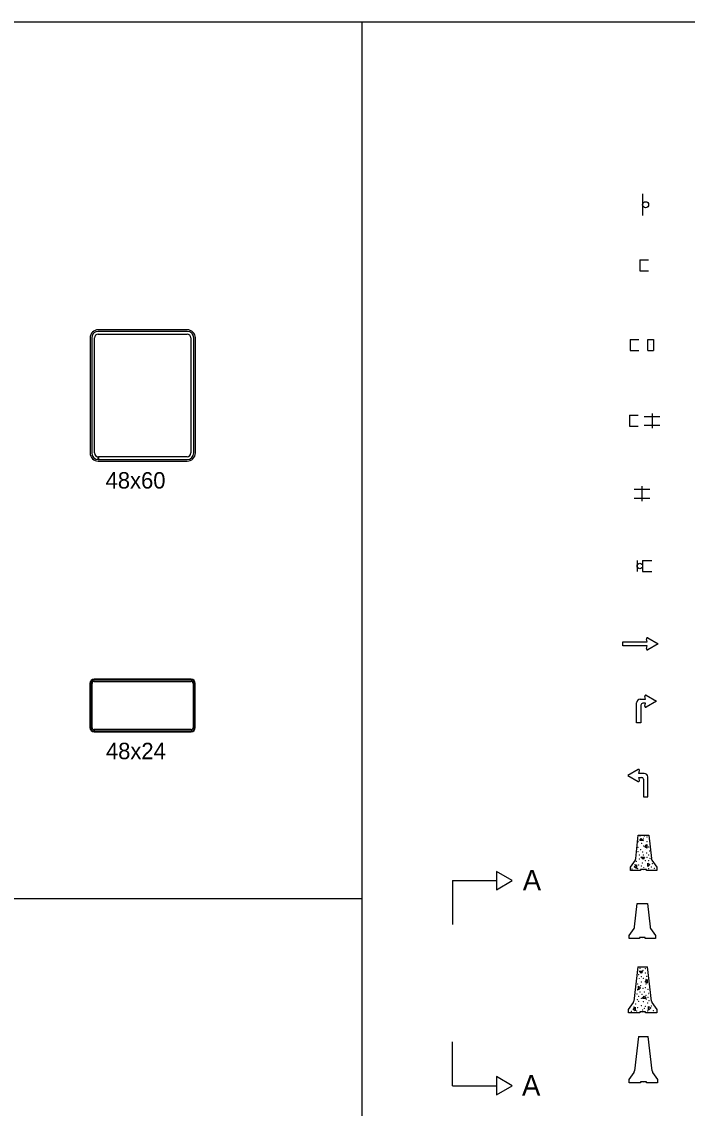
# Model space of a CAD drawing. Extents: x 1458 to 4498, y 17709 to 24109.
# Drawn here: x 2268 to 2875, y 18718 to 19709 of the extents above; entities that cross this region are included whole.
import ezdxf

# ---------------------------------------------------------------- set-up
doc = ezdxf.new("R2010")
doc.units = 0
for name, color, linetype in [('P_ODOT_PLAN_General', 7, 'Continuous'), ('P_ODOT_PLAN_TBlock', 7, 'Continuous'), ('P_TRAF_TCP_General', 7, 'Continuous')]:
    doc.layers.add(name, color=color, linetype=linetype)

msp = doc.modelspace()

# ---------------------------------------------------------------- linework, layer by layer
at = {"layer": 'P_ODOT_PLAN_General'}
for p, q in [((2661.02, 18925.46), (2701.02, 18925.46)), ((2661.02, 18925.46), (2661.02, 18885.46)), ((2701.02, 18925.46), (2701.02, 18925.46)), ((2661.03, 18738.18), (2661.03, 18778.18)), ((2661.03, 18738.18), (2701.03, 18738.18)), ((2701.03, 18738.18), (2701.03, 18738.18))]:
    msp.add_line(p, q, dxfattribs=at)
for points in [[(2701.02, 18917.1), (2715.51, 18925.46), (2701.02, 18933.82)], [(2715.51, 18738.18), (2701.03, 18746.54), (2701.03, 18729.82)]]:
    msp.add_lwpolyline(points, close=True, dxfattribs=at)
at = {"layer": 'P_ODOT_PLAN_TBlock'}
for p, q in [((2578.44, 19709.14), (2578.44, 17709.14)), ((1458.44, 18909.14), (2578.44, 18909.14))]:
    msp.add_line(p, q, dxfattribs=at)
at = {"layer": 'P_TRAF_TCP_General'}
for p, q in [((2834.32, 19552.16), (2834.32, 19532.17)), ((2831.66, 19491.76), (2831.66, 19481.77)), ((2831.66, 19491.76), (2839.66, 19491.76)), ((2831.66, 19486.76), (2831.66, 19486.76)), ((2831.66, 19481.77), (2839.66, 19481.77)), ((2419.02, 19428.1), (2338.05, 19428.1)), ((2419.02, 19426.6), (2338.05, 19426.6)), ((2338.05, 19424.1), (2419.02, 19424.1)), ((2330.55, 19420.6), (2330.55, 19315.64)), ((2332.05, 19420.6), (2332.05, 19315.64)), ((2334.55, 19315.64), (2334.55, 19420.6)), ((2422.52, 19420.6), (2422.52, 19315.64)), ((2425.02, 19315.64), (2425.02, 19420.6)), ((2426.52, 19315.64), (2426.52, 19420.6)), ((2822.99, 19419.26), (2822.99, 19409.27)), ((2822.99, 19419.26), (2830.99, 19419.26)), ((2838.99, 19409.27), (2838.99, 19419.29)), ((2838.99, 19419.29), (2844.18, 19419.29)), ((2841.59, 19414.28), (2841.59, 19414.28)), ((2844.18, 19419.29), (2844.18, 19409.27)), ((2822.99, 19409.27), (2830.99, 19409.27)), ((2838.99, 19409.27), (2844.18, 19409.27)), ((2822.28, 19350.05), (2822.28, 19340.06)), ((2822.28, 19350.05), (2830.27, 19350.05)), ((2822.28, 19345.06), (2822.28, 19345.06)), ((2835.72, 19348.94), (2850.11, 19348.94)), ((2842.92, 19351.74), (2842.92, 19338.15)), ((2822.28, 19340.06), (2830.27, 19340.06)), ((2835.72, 19340.94), (2850.11, 19340.94)), ((2338.05, 19309.64), (2338.05, 19312.14)), ((2338.05, 19308.14), (2419.02, 19308.14)), ((2419.02, 19312.14), (2338.08, 19312.14)), ((2338.08, 19312.14), (2338.08, 19309.64)), ((2338.08, 19309.64), (2419.02, 19309.64)), ((2833.69, 19285.32), (2833.69, 19271.72)), ((2826.49, 19282.52), (2840.89, 19282.52)), ((2826.49, 19274.52), (2840.89, 19274.52)), ((2829.29, 19217.49), (2829.29, 19207.49)), ((2834.37, 19217.49), (2842.73, 19217.49)), ((2834.37, 19217.49), (2834.37, 19207.49)), ((2834.37, 19212.49), (2834.37, 19212.49)), ((2834.37, 19207.49), (2842.73, 19207.49)), ((2839.1, 19146.83), (2848.47, 19141.42)), ((2816.18, 19143.27), (2838.43, 19143.27)), ((2816.18, 19139.58), (2816.18, 19143.27)), ((2838.43, 19139.58), (2816.18, 19139.58)), ((2838.43, 19143.27), (2837.75, 19145.8)), ((2837.75, 19137.05), (2838.43, 19139.58)), ((2848.47, 19141.42), (2839.1, 19136.01)), ((2422.66, 19109.15), (2334.2, 19109.15)), ((2422.66, 19108.4), (2334.2, 19108.4)), ((2334.2, 19107.15), (2422.66, 19107.15)), ((2330.45, 19105.4), (2330.45, 19064.91)), ((2331.2, 19105.4), (2331.2, 19064.91)), ((2332.45, 19064.91), (2332.45, 19105.4)), ((2424.41, 19105.4), (2424.41, 19064.91)), ((2425.66, 19064.91), (2425.66, 19105.4)), ((2426.41, 19064.91), (2426.41, 19105.4)), ((2836.95, 19090.93), (2836.27, 19093.46)), ((2836.27, 19084.71), (2836.95, 19087.24)), ((2837.62, 19094.5), (2847, 19089.09)), ((2847, 19089.09), (2837.62, 19083.68)), ((2334.2, 19061.92), (2334.2, 19063.17)), ((2334.2, 19061.17), (2422.66, 19061.17)), ((2422.66, 19063.17), (2334.21, 19063.17)), ((2334.21, 19063.17), (2334.21, 19061.92)), ((2334.21, 19061.92), (2422.66, 19061.92)), ((2830.27, 19026.79), (2820.9, 19021.37)), ((2820.9, 19021.37), (2830.27, 19015.96)), ((2830.95, 19023.22), (2831.63, 19025.75)), ((2831.63, 19017), (2830.95, 19019.53)), ((2828.05, 18945.41), (2830.42, 18966.74)), ((2830.42, 18966.74), (2839.92, 18966.74)), ((2830.58, 18961.22), (2830.86, 18960.94)), ((2830.86, 18961.22), (2830.58, 18960.94)), ((2831.87, 18966.21), (2832.16, 18965.93)), ((2832.16, 18966.21), (2831.87, 18965.93)), ((2833.29, 18959.59), (2833.57, 18959.31)), ((2833.57, 18959.59), (2833.29, 18959.31)), ((2834.92, 18963.95), (2835.21, 18963.67)), ((2835.21, 18963.95), (2834.92, 18963.67)), ((2835.76, 18966.31), (2836.05, 18966.03)), ((2836.05, 18966.31), (2835.76, 18966.03)), ((2838.16, 18965.27), (2838.44, 18965)), ((2838.44, 18965.27), (2838.16, 18965)), ((2838.16, 18961.07), (2838.44, 18960.8)), ((2838.44, 18961.07), (2838.16, 18960.8)), ((2839.92, 18966.74), (2842.3, 18945.41)), ((2829.97, 18952.01), (2830.25, 18951.73)), ((2830.25, 18952.01), (2829.97, 18951.73)), ((2830.13, 18955.82), (2830.42, 18955.54)), ((2830.42, 18955.82), (2830.13, 18955.54)), ((2831.14, 18948.91), (2831.42, 18948.63)), ((2831.42, 18948.91), (2831.14, 18948.63)), ((2832.5, 18953.78), (2832.79, 18953.5)), ((2832.79, 18953.78), (2832.5, 18953.5)), ((2834.37, 18951.62), (2834.65, 18951.34)), ((2834.65, 18951.62), (2834.37, 18951.34)), ((2834.92, 18948.75), (2835.21, 18948.47)), ((2835.21, 18948.75), (2834.92, 18948.47)), ((2835.28, 18957.13), (2835.57, 18956.85)), ((2835.57, 18957.13), (2835.28, 18956.85)), ((2836.53, 18953.9), (2836.82, 18953.62)), ((2836.82, 18953.9), (2836.53, 18953.62)), ((2837.98, 18950.66), (2838.26, 18950.38)), ((2838.26, 18950.66), (2837.98, 18950.38)), ((2839.78, 18956.17), (2840.07, 18955.89)), ((2840.07, 18956.17), (2839.78, 18955.89)), ((2839.78, 18948.91), (2840.07, 18948.63)), ((2840.07, 18948.91), (2839.78, 18948.63)), ((2840.58, 18952.48), (2840.87, 18952.2)), ((2840.87, 18952.48), (2840.58, 18952.2)), ((2823.18, 18937.75), (2827.72, 18944.06)), ((2823.18, 18934.75), (2823.18, 18937.75)), ((2827.15, 18940.07), (2827.44, 18939.79)), ((2827.44, 18940.07), (2827.15, 18939.79)), ((2828.56, 18942.98), (2828.85, 18942.71)), ((2828.85, 18942.98), (2828.56, 18942.71)), ((2830.58, 18939.64), (2830.86, 18939.36)), ((2830.86, 18939.64), (2830.58, 18939.36)), ((2831.34, 18945.31), (2831.63, 18945.03)), ((2831.63, 18945.31), (2831.34, 18945.03)), ((2833.14, 18938.79), (2833.43, 18938.52)), ((2833.43, 18938.79), (2833.14, 18938.52)), ((2833.94, 18941.5), (2834.22, 18941.22)), ((2834.22, 18941.5), (2833.94, 18941.22)), ((2836.67, 18943.71), (2836.96, 18943.43)), ((2836.96, 18943.71), (2836.67, 18943.43)), ((2838.25, 18946.72), (2838.54, 18946.44)), ((2838.54, 18946.72), (2838.25, 18946.44)), ((2839.6, 18943.75), (2839.89, 18943.47)), ((2839.89, 18943.75), (2839.6, 18943.47)), ((2842.06, 18937.91), (2842.35, 18937.63)), ((2842.35, 18937.91), (2842.06, 18937.63)), ((2842.63, 18944.06), (2847.17, 18937.75)), ((2842.96, 18941.12), (2843.24, 18940.84)), ((2843.24, 18941.12), (2842.96, 18940.84)), ((2847.17, 18937.75), (2847.17, 18934.75)), ((2832.47, 18934.75), (2823.18, 18934.75)), ((2824.62, 18936.13), (2824.91, 18935.85)), ((2824.91, 18936.13), (2824.62, 18935.85)), ((2829.58, 18936.48), (2829.87, 18936.21)), ((2829.87, 18936.48), (2829.58, 18936.21)), ((2837.87, 18935.63), (2832.47, 18935.63)), ((2832.47, 18935.63), (2832.47, 18934.75)), ((2835, 18937.53), (2835.29, 18937.26)), ((2835.29, 18937.53), (2835, 18937.26)), ((2835.17, 18934.75), (2835.17, 18934.75)), ((2837.87, 18934.75), (2837.87, 18935.63)), ((2847.17, 18934.75), (2837.87, 18934.75)), ((2839.6, 18936.4), (2839.89, 18936.12)), ((2839.89, 18936.4), (2839.6, 18936.12)), ((2844.84, 18936.75), (2845.12, 18936.47)), ((2845.12, 18936.75), (2844.84, 18936.47)), ((2826.99, 18883.11), (2829.36, 18904.43)), ((2829.36, 18904.43), (2838.86, 18904.43)), ((2838.86, 18904.43), (2841.23, 18883.11)), ((2822.12, 18875.44), (2826.65, 18881.75)), ((2841.57, 18881.75), (2846.11, 18875.44)), ((2822.12, 18872.44), (2822.12, 18875.44)), ((2831.41, 18872.44), (2822.12, 18872.44)), ((2836.81, 18873.33), (2831.41, 18873.33)), ((2831.41, 18873.33), (2831.41, 18872.44)), ((2834.11, 18872.44), (2834.11, 18872.44)), ((2836.81, 18872.44), (2836.81, 18873.33)), ((2846.11, 18872.44), (2836.81, 18872.44)), ((2846.11, 18875.44), (2846.11, 18872.44)), ((2829.86, 18846.77), (2826.24, 18815.45)), ((2829.86, 18846.77), (2838.86, 18846.77)), ((2830.61, 18839.77), (2830.89, 18839.5)), ((2830.89, 18839.77), (2830.61, 18839.5)), ((2831.86, 18845.39), (2832.15, 18845.11)), ((2832.15, 18845.39), (2831.86, 18845.11)), ((2834.57, 18843.75), (2834.86, 18843.47)), ((2834.86, 18843.75), (2834.57, 18843.47)), ((2836.56, 18841.29), (2836.85, 18841.01)), ((2836.85, 18841.29), (2836.56, 18841.01)), ((2836.79, 18845.3), (2837.07, 18845.02)), ((2837.07, 18845.3), (2836.79, 18845.02)), ((2842.49, 18815.45), (2838.86, 18846.77)), ((2829.77, 18831.26), (2830.05, 18830.98)), ((2830.05, 18831.26), (2829.77, 18830.98)), ((2831.06, 18836.25), (2831.34, 18835.97)), ((2831.34, 18836.25), (2831.06, 18835.97)), ((2832.48, 18829.62), (2832.76, 18829.34)), ((2832.76, 18829.62), (2832.48, 18829.34)), ((2832.98, 18837.73), (2833.26, 18837.45)), ((2833.26, 18837.73), (2832.98, 18837.45)), ((2833.13, 18833.12), (2833.41, 18832.84)), ((2833.41, 18833.12), (2833.13, 18832.84)), ((2834.95, 18836.35), (2835.24, 18836.06)), ((2835.24, 18836.35), (2834.95, 18836.06)), ((2837.35, 18835.31), (2837.63, 18835.03)), ((2837.63, 18835.31), (2837.35, 18835.03)), ((2837.35, 18831.11), (2837.63, 18830.83)), ((2837.63, 18831.11), (2837.35, 18830.83)), ((2837.82, 18838.06), (2838.11, 18837.78)), ((2838.11, 18838.06), (2837.82, 18837.78)), ((2829.16, 18822.05), (2829.44, 18821.77)), ((2829.44, 18822.05), (2829.16, 18821.77)), ((2829.32, 18825.86), (2829.6, 18825.58)), ((2829.6, 18825.86), (2829.32, 18825.58)), ((2830.67, 18820), (2830.96, 18819.72)), ((2830.96, 18820), (2830.67, 18819.72)), ((2831.69, 18823.81), (2831.97, 18823.53)), ((2831.97, 18823.81), (2831.69, 18823.53)), ((2833.56, 18821.66), (2833.84, 18821.38)), ((2833.84, 18821.66), (2833.56, 18821.38)), ((2834.47, 18827.16), (2834.76, 18826.88)), ((2834.76, 18827.16), (2834.47, 18826.88)), ((2835.72, 18823.93), (2836.01, 18823.65)), ((2836.01, 18823.93), (2835.72, 18823.65)), ((2836.79, 18827.89), (2837.07, 18827.61)), ((2837.07, 18827.89), (2836.79, 18827.61)), ((2837.17, 18820.7), (2837.45, 18820.42)), ((2837.45, 18820.7), (2837.17, 18820.42)), ((2838.97, 18826.21), (2839.26, 18825.93)), ((2839.26, 18826.21), (2838.97, 18825.93)), ((2838.97, 18818.94), (2839.26, 18818.67)), ((2839.26, 18818.94), (2838.97, 18818.67)), ((2839.77, 18822.51), (2840.06, 18822.23)), ((2840.06, 18822.51), (2839.77, 18822.23)), ((2821.37, 18807.78), (2825.91, 18814.09)), ((2826.34, 18810.11), (2826.63, 18809.83)), ((2826.63, 18810.11), (2826.34, 18809.83)), ((2827.75, 18813.02), (2828.04, 18812.74)), ((2828.04, 18813.02), (2827.75, 18812.74)), ((2829.29, 18816.83), (2829.58, 18816.56)), ((2829.58, 18816.83), (2829.29, 18816.56)), ((2829.77, 18809.67), (2830.05, 18809.39)), ((2830.05, 18809.67), (2829.77, 18809.39)), ((2830.53, 18815.35), (2830.82, 18815.07)), ((2830.82, 18815.35), (2830.53, 18815.07)), ((2833.11, 18817.98), (2833.39, 18817.7)), ((2833.39, 18817.98), (2833.11, 18817.7)), ((2833.13, 18811.53), (2833.41, 18811.25)), ((2833.41, 18811.53), (2833.13, 18811.25)), ((2834.95, 18815.07), (2835.24, 18814.79)), ((2835.24, 18815.07), (2834.95, 18814.79)), ((2835.79, 18808.94), (2836.08, 18808.66)), ((2836.08, 18808.94), (2835.79, 18808.66)), ((2836.75, 18810.72), (2837.03, 18810.44)), ((2837.03, 18810.72), (2836.75, 18810.44)), ((2837.44, 18816.76), (2837.73, 18816.48)), ((2837.73, 18816.76), (2837.44, 18816.48)), ((2838.79, 18813.78), (2839.08, 18813.5)), ((2839.08, 18813.78), (2838.79, 18813.5)), ((2842.15, 18811.16), (2842.43, 18810.88)), ((2842.43, 18811.16), (2842.15, 18810.88)), ((2842.82, 18814.09), (2847.36, 18807.78)), ((2821.37, 18804.78), (2821.37, 18807.78)), ((2831.66, 18804.78), (2821.37, 18804.78)), ((2823.81, 18806.17), (2824.1, 18805.89)), ((2824.1, 18806.17), (2823.81, 18805.89)), ((2828.77, 18806.52), (2829.06, 18806.24)), ((2829.06, 18806.52), (2828.77, 18806.24)), ((2837.06, 18805.67), (2831.66, 18805.67)), ((2831.66, 18805.67), (2831.66, 18804.78)), ((2834.19, 18807.57), (2834.48, 18807.29)), ((2834.48, 18807.57), (2834.19, 18807.29)), ((2834.36, 18804.78), (2834.36, 18804.78)), ((2837.06, 18804.78), (2837.06, 18805.67)), ((2847.36, 18804.78), (2837.06, 18804.78)), ((2838.79, 18806.43), (2839.08, 18806.15)), ((2839.08, 18806.43), (2838.79, 18806.15)), ((2844.02, 18806.78), (2844.31, 18806.5)), ((2844.31, 18806.78), (2844.02, 18806.5)), ((2847.36, 18807.78), (2847.36, 18804.78)), ((2830.54, 18782.98), (2826.92, 18751.66)), ((2830.54, 18782.98), (2839.54, 18782.98)), ((2843.16, 18751.66), (2839.54, 18782.98)), ((2822.04, 18743.99), (2826.58, 18750.3)), ((2843.5, 18750.3), (2848.03, 18743.99)), ((2822.04, 18740.99), (2822.04, 18743.99)), ((2832.34, 18740.99), (2822.04, 18740.99)), ((2837.74, 18741.88), (2832.34, 18741.88)), ((2832.34, 18741.88), (2832.34, 18740.99)), ((2835.04, 18740.99), (2835.04, 18740.99)), ((2837.74, 18740.99), (2837.74, 18741.88)), ((2848.03, 18740.99), (2837.74, 18740.99)), ((2848.03, 18743.99), (2848.03, 18740.99))]:
    msp.add_line(p, q, dxfattribs=at)
for points in [[(1458.44, 19709.14), (4498.44, 19709.14), (4498.44, 17709.14), (1458.44, 17709.14)], [(2831.81, 18962), (2833.11, 18963.89), (2835.05, 18962)], [(2838.19, 18955.05), (2836.31, 18956.35), (2838.19, 18958.29)], [(2828.67, 18936.57), (2826.78, 18937.87), (2828.67, 18939.81)], [(2836.01, 18946.75), (2834.72, 18944.86), (2832.78, 18946.75)], [(2839.09, 18941.42), (2840.98, 18940.13), (2839.09, 18938.19)], [(2834.29, 18842.67), (2832.99, 18840.78), (2831.05, 18842.67)], [(2830.65, 18828.91), (2832.54, 18827.62), (2830.65, 18825.68)], [(2838.42, 18831.8), (2836.54, 18833.09), (2838.42, 18835.03)], [(2834.35, 18817.94), (2835.65, 18819.83), (2837.59, 18817.94)], [(2827.66, 18806.53), (2825.78, 18807.82), (2827.66, 18809.77)], [(2839.82, 18810.49), (2841.71, 18809.19), (2839.82, 18807.25)]]:
    msp.add_lwpolyline(points, close=True, dxfattribs=at)
for points in [[(2832.85, 19085.61), (2832.85, 19069.5), (2828.89, 19069.5), (2828.89, 19087.65)], [(2832.17, 19090.93), (2836.95, 19090.93)], [(2836.95, 19087.24), (2834.49, 19087.24)], [(2835.73, 19023.22), (2830.95, 19023.22)], [(2830.95, 19019.53), (2833.41, 19019.53)], [(2835.04, 19017.89), (2835.04, 19001.79), (2839, 19001.79), (2839, 19019.94)], [(2840.88, 18945.88), (2841.15, 18945.62)], [(2841.13, 18945.87), (2840.89, 18945.63)], [(2840.07, 18815.91), (2840.34, 18815.66)], [(2840.32, 18815.9), (2840.08, 18815.67)]]:
    msp.add_lwpolyline(points, dxfattribs=at)
for centre, radius in [((2837.07, 19542.17), 2.75), ((2831.83, 19212.49), 2.54)]:
    msp.add_circle(centre, radius, dxfattribs=at)
for centre, radius, start, end in [((2338.05, 19420.6), 7.5, 90, 180), ((2338.05, 19420.6), 6, 90, 180), ((2338.05, 19420.6), 3.5, 90, 180), ((2419.02, 19420.6), 7.5, 0, 90), ((2419.02, 19420.6), 6, 0, 90), ((2419.02, 19420.6), 3.5, 0, 90), ((2338.05, 19315.64), 7.5, 180, 270), ((2338.05, 19315.64), 6, 180, 270), ((2338.05, 19315.64), 3.5, 180, 270), ((2419.02, 19315.64), 6, 270, 0), ((2419.02, 19315.64), 3.5, 270, 0), ((2419.02, 19315.64), 7.5, 270, 0), ((2838.64, 19146.04), 0.923, 60.00539, 195.00513), ((2838.64, 19136.81), 0.923, 164.99677, 300.00026), ((2334.2, 19105.4), 3.75, 90, 180), ((2334.2, 19105.4), 3, 90, 180), ((2334.2, 19105.4), 1.75, 90, 180), ((2422.66, 19105.4), 3.75, 0, 90), ((2422.66, 19105.4), 3, 0, 90), ((2422.66, 19105.4), 1.75, 0, 90), ((2832.17, 19087.65), 3.28, 90, 180), ((2834.49, 19085.61), 1.64, 90, 180), ((2837.16, 19093.7), 0.923, 60.00539, 195.00513), ((2837.16, 19084.47), 0.923, 164.99677, 300.00026), ((2334.2, 19064.91), 3.75, 180, 270), ((2334.2, 19064.91), 3, 180, 270), ((2334.2, 19064.91), 1.75, 180, 270), ((2422.66, 19064.91), 3, 270, 0), ((2422.66, 19064.91), 1.75, 270, 0), ((2422.66, 19064.91), 3.75, 270, 0), ((2830.73, 19025.99), 0.923, 344.99487, 119.99461), ((2833.41, 19017.89), 1.64, 0, 90), ((2835.73, 19019.94), 3.28, 0, 90), ((2830.73, 19016.76), 0.923, 239.99974, 15.00323), ((2818.2, 18947.13), 10, 342.10838, 350.12325), ((2852.14, 18947.13), 10, 189.87675, 197.89162), ((2817.14, 18884.82), 10, 342.10838, 350.12325), ((2851.08, 18884.82), 10, 189.87675, 197.89162), ((2816.39, 18817.16), 10, 342.10838, 350.12325), ((2852.33, 18817.16), 10, 189.87675, 197.89162), ((2817.07, 18753.37), 10, 342.10838, 350.12325), ((2853.01, 18753.37), 10, 189.87675, 197.89162)]:
    msp.add_arc(centre, radius, start, end, dxfattribs=at)

# ---------------------------------------------------------------- texts
at = {"layer": 'P_ODOT_PLAN_General'}
for p in [(2725.09, 18916.46), (2724.39, 18729.24)]:
    msp.add_text('A', height=18.72, rotation=359.99975, dxfattribs=at).set_placement(p)
at = {"layer": 'P_TRAF_TCP_General'}
for s, p in [('48x60', (2344.69, 19283.15)), ('48x24', (2344.99, 19036.18))]:
    msp.add_text(s, height=14.994, dxfattribs=at).set_placement(p)

doc.saveas('drawing.dxf')
